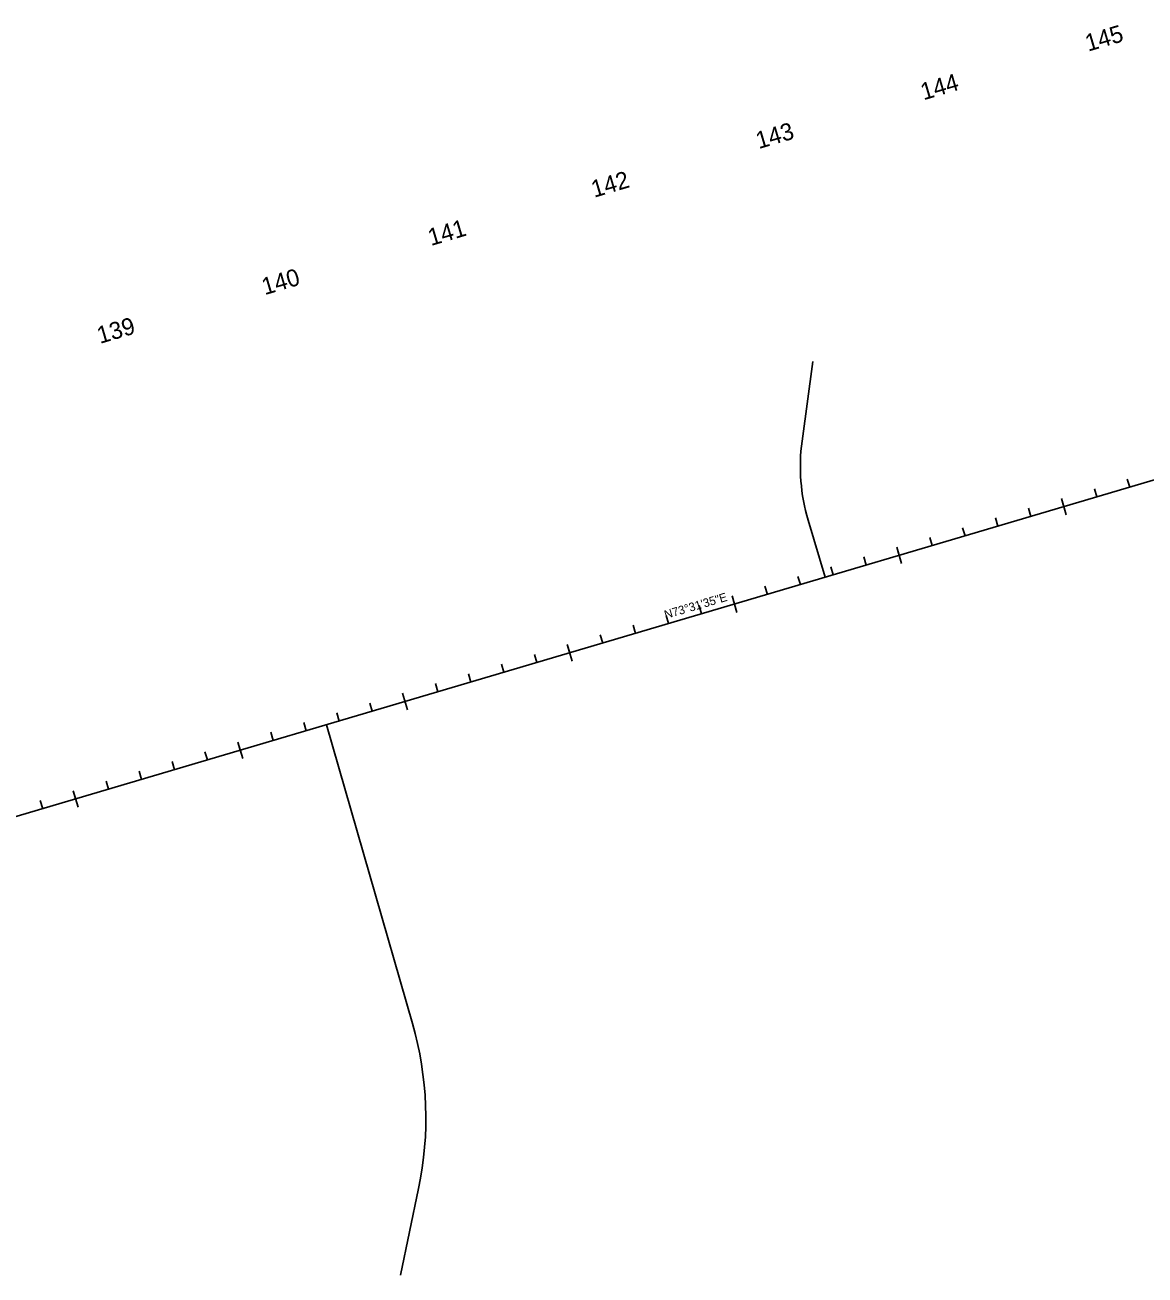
# Model space of a CAD drawing. Extents: x 1699999 to 1705087, y 475568 to 482652.
# Drawn here: x 1703786 to 1704438, y 477746 to 478474 of the extents above; entities that cross this region are included whole.
import ezdxf

# ---------------------------------------------------------------- set-up
doc = ezdxf.new("R2010")
doc.units = 0
for name, color, linetype in [('Default', 7, 'Continuous'), ('DES - DTM - Ground', 7, 'Continuous'), ('DES - DTM - Points - High', 7, 'Continuous'), ('DESIGN - TYPICAL - Guardrail', 7, 'Continuous'), ('TC_Aggregate', 7, 'Continuous')]:
    doc.layers.add(name, color=color, linetype=linetype)

msp = doc.modelspace()

# ---------------------------------------------------------------- linework, layer by layer
at = {"layer": 'Default'}
for p, q in [((1704244.49, 478278.03), (1704238.23, 478231.59)), ((1704241.77, 478185.63), (1704251.61, 478152.36)), ((1703961.27, 478066.51), (1704011.36, 477892.7)), ((1704014.98, 477796.53), (1704004.5, 477746.2))]:
    msp.add_line(p, q, dxfattribs=at)
for centre, radius, start, end in [((1704347.43, 478216.87), 110.18, 172.32337, 196.47351), ((1703819.18, 477837.31), 200, 348.23366, 16.07743)]:
    msp.add_arc(centre, radius, start, end, dxfattribs=at)
at = {"layer": 'DES - DTM - Ground'}
for p, q in [((1703472.49, 477921.97), (1704846.87, 478328.39)), ((1704244.49, 478278.03), (1704238.23, 478231.59)), ((1704241.77, 478185.63), (1704251.61, 478152.36)), ((1703961.27, 478066.51), (1704011.36, 477892.7)), ((1704014.98, 477796.53), (1704004.5, 477746.2))]:
    msp.add_line(p, q, dxfattribs=at)
for centre, radius, start, end in [((1704347.43, 478216.87), 110.18, 172.32337, 196.47351), ((1703819.18, 477837.31), 200, 348.23366, 16.07743)]:
    msp.add_arc(centre, radius, start, end, dxfattribs=at)
at = {"layer": 'DES - DTM - Points - High'}
for p, q in [((1704429.02, 478204.83), (1704427.6, 478209.6)), ((1704389.24, 478198.28), (1704392.08, 478188.69)), ((1704409.84, 478199.15), (1704408.42, 478203.93)), ((1704371.48, 478187.81), (1704370.07, 478192.59)), ((1704352.3, 478182.14), (1704350.89, 478186.92)), ((1704333.12, 478176.47), (1704331.71, 478181.24)), ((1704293.35, 478169.92), (1704296.18, 478160.33)), ((1704313.94, 478170.8), (1704312.53, 478175.57)), ((1704275.58, 478159.45), (1704274.17, 478164.23)), ((1704256.4, 478153.78), (1704254.99, 478158.56)), ((1704237.23, 478148.11), (1704235.81, 478152.89)), ((1704197.45, 478141.56), (1704200.29, 478131.97)), ((1704218.05, 478142.44), (1704216.63, 478147.22)), ((1704179.69, 478131.1), (1704178.28, 478135.87)), ((1704160.51, 478125.43), (1704159.1, 478130.2)), ((1704122.15, 478114.08), (1704120.74, 478118.86)), ((1704141.33, 478119.75), (1704139.92, 478124.53)), ((1704101.55, 478113.21), (1704104.39, 478103.62)), ((1704083.79, 478102.74), (1704082.38, 478107.52)), ((1704064.61, 478097.07), (1704063.2, 478101.84)), ((1704026.26, 478085.73), (1704024.84, 478090.5)), ((1704045.44, 478091.4), (1704044.02, 478096.17)), ((1704005.66, 478084.85), (1704008.5, 478075.26)), ((1703987.9, 478074.38), (1703986.49, 478079.16)), ((1703949.54, 478063.04), (1703948.13, 478067.82)), ((1703968.72, 478068.71), (1703967.31, 478073.49)), ((1703930.36, 478057.37), (1703928.95, 478062.14)), ((1703909.76, 478056.49), (1703912.6, 478046.9)), ((1703892, 478046.03), (1703890.59, 478050.8)), ((1703853.65, 478034.68), (1703852.23, 478039.46)), ((1703872.82, 478040.35), (1703871.41, 478045.13)), ((1703834.47, 478029.01), (1703833.05, 478033.79)), ((1703813.87, 478028.13), (1703816.71, 478018.54)), ((1703796.11, 478017.67), (1703794.7, 478022.44))]:
    msp.add_line(p, q, dxfattribs=at)
at = {"layer": 'DESIGN - TYPICAL - Guardrail'}
for p, q in [((1704390.66, 478193.48), (1704389.25, 478198.26)), ((1704294.76, 478165.13), (1704293.35, 478169.9)), ((1704198.87, 478136.77), (1704197.46, 478141.54)), ((1704102.97, 478108.41), (1704101.56, 478113.19)), ((1704005.66, 478084.85), (1704008.5, 478075.24)), ((1703911.18, 478051.7), (1703909.77, 478056.47)), ((1703815.29, 478023.34), (1703813.88, 478028.12))]:
    msp.add_line(p, q, dxfattribs=at)

# ---------------------------------------------------------------- texts
at = {"layer": 'DES - DTM - Points - High'}
for s, p in [('145', (1704404.8, 478458.37)), ('144', (1704308.96, 478430.03)), ('143', (1704213.04, 478401.66)), ('142', (1704117.2, 478373.32)), ('141', (1704022.18, 478345.22)), ('140', (1703925.38, 478316.6)), ('139', (1703829.46, 478288.23))]:
    msp.add_text(s, height=9.96, rotation=16.47351, dxfattribs=at).set_placement(p)
at = {"layer": 'DESIGN - TYPICAL - Guardrail'}
for s, p in [('145', (1704404.8, 478458.37)), ('140', (1703925.38, 478316.6))]:
    msp.add_text(s, height=9.96, rotation=16.47351, dxfattribs=at).set_placement(p)
at = {"layer": 'TC_Aggregate'}
msp.add_text('N73°31\'35"E', height=4.98, rotation=16.47351, dxfattribs=at).set_placement((1704158.83, 478128.06))

doc.saveas('drawing.dxf')
